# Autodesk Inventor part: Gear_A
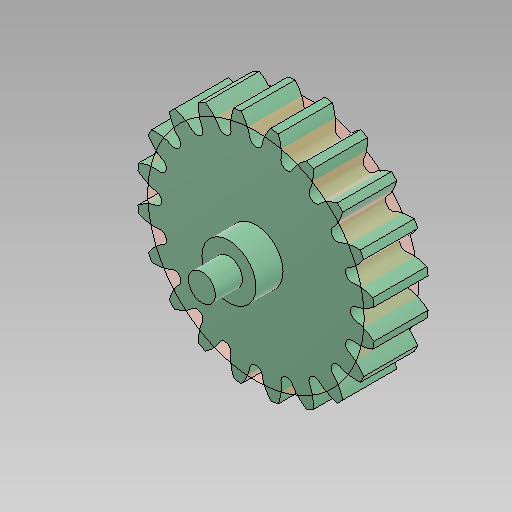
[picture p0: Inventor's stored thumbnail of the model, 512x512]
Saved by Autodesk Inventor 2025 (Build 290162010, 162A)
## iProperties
Created: 2024-10
Part Number: Gear_A
Material: Generic
Document SubType Name: Modeling
Designer: Dennis
Mass: 12.9046 g
Surface Area: 51.6705 cm^2
Volume: 12.9046 cm^3
Density: 1 g/cm^3
Appearance: Smooth - Dark Sea Green
Author: Dennis
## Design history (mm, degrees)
sketch "Sketch1"
  geometry: C1 r 17.5 at (0, 0) reference; C2 r 18.794 at (0, 0) reference; C3 r 20 at (0, 0) reference; A1 r 22 centre (0, 0) between (-2.754, 21.827) and (2.754, 21.827) reference; 54 further points
  constraints: 4 centre point, 2 point on circle, 115 other
extrude "Extrusion1" join sketch "Sketch1" distance "d0" = 10 (= FaceWidth); taper "d1" = 0 deg
extrude "Extrusion2" cut sketch "Sketch1" extent not by distance; stored distance "d2" = 0; taper "d3" = 0 deg
sketch "Sketch2"
  geometry: L1 (0, 0)-(0, 10); L2 (0, 10)-(2.5, 10); L3 (2.5, 10)-(2.5, 5); L4 (2.5, 5)-(5, 5); L5 (5, 5)-(5, 0); L6 (0, 0)-(5, 0)
  constraints: 12 end point, 4 perpendicular, 1 horizontal, 1 parallel, 1 vertical
  dimensions: "d7" = 5 diameter of L3 L1; "d8" = 10 diameter of L5 L1; "d9" = 5 distance of L4.end L5.end
revolve "Revolution1" sketch "Sketch2" stored, may be unused: angle "d10" = 90 deg
sketch "Sketch3"
  geometry: C1 r 20 at (0, 0); 1 further point
  constraints: 1 centre point, 1 coincident
  dimensions: "d11" = 40 diameter of C1
extrude_surface "ExtrusionSrf1" sketch "Sketch3" dims "d12" = 10, "d13" = 0
body "Solid1"
pattern_circular "Circular Pattern1" dims angle "d5" = 360 deg
body "Srf1"
other parameters: "Module" = 2 [user parameter], "PressureAngle" = 20 deg [user parameter], "UnitProfileClearance" = 2.5 [user parameter], "UnitRoundRadius" = 3.5 [user parameter], "HeadDiameter" = 44 [user parameter], "RootDiameter" = 35 [user parameter], "BaseDiameter" = 37.5877 [user parameter], "FaceWidth" = 10 [user parameter; used in 1 equation term], "HelixAngle" = 0 [user parameter], "UnitCorrection" = 0 [user parameter], "UnitAddendumModification" = 0 [user parameter], "CircularPitch" = 36 deg [user parameter], "UnitBacklashShift" = 0 [user parameter], "TotalToolShift" = 0 [user parameter], "IsInternal" = 0 [user parameter]
